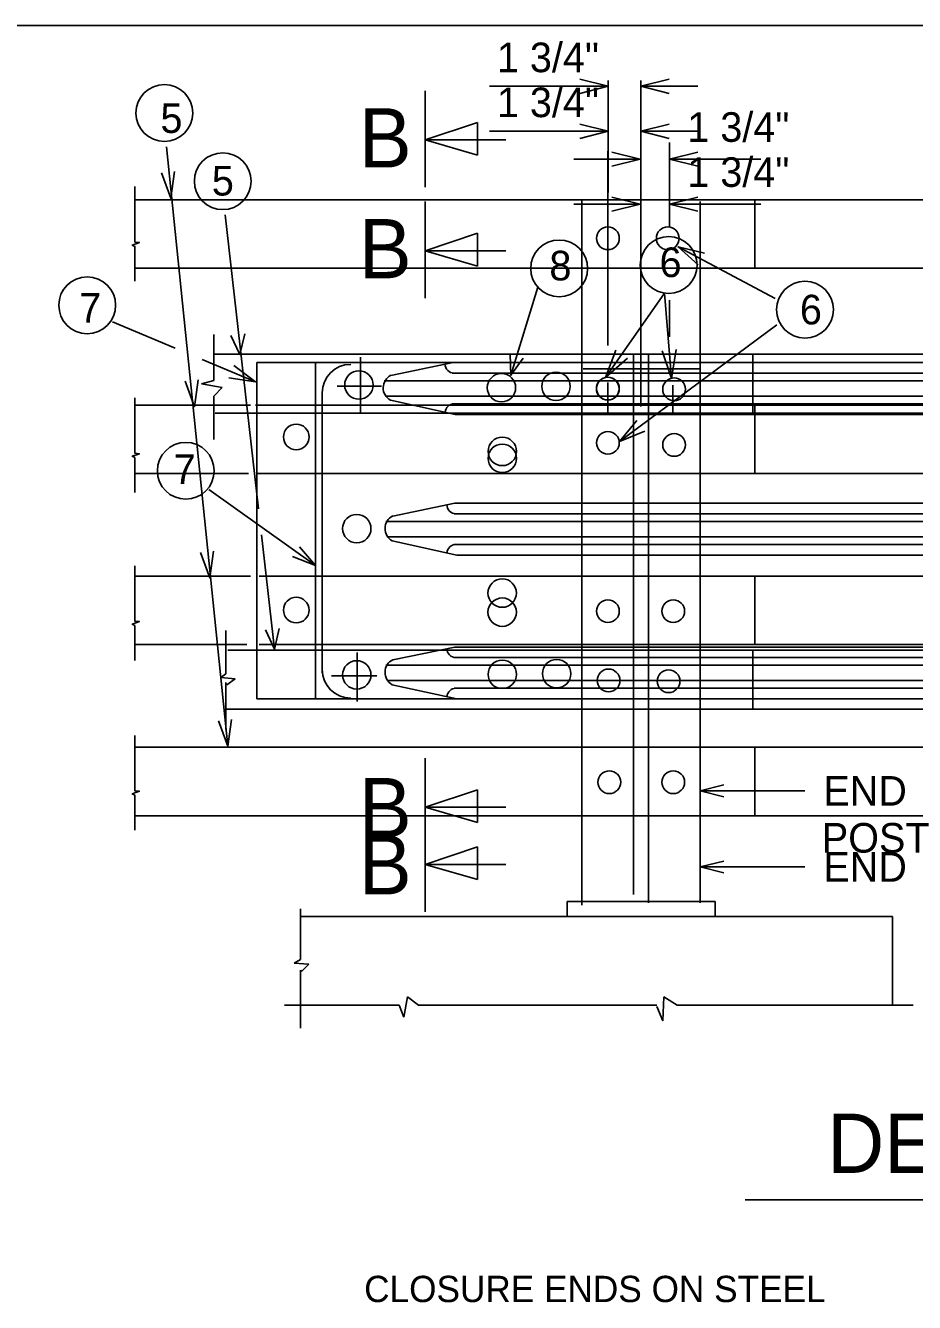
# Model space of a CAD drawing. Extents: x 1509.2 to 1521.3, y 1506 to 1514.6.
# Drawn here: x 1512.741 to 1514.148, y 1511.909 to 1513.931 of the extents above; entities that cross this region are included whole.
import ezdxf

# ---------------------------------------------------------------- set-up
doc = ezdxf.new("R2010")
doc.units = 0
for name, color, linetype in [('Level 1', 7, 'Continuous'), ('Level 2', 7, 'Continuous'), ('Level 3', 7, 'Continuous'), ('Level 4', 7, 'Continuous')]:
    doc.layers.add(name, color=color, linetype=linetype)

msp = doc.modelspace()

# ---------------------------------------------------------------- linework, layer by layer
at = {"layer": 'Level 1'}
msp.add_line((1520.7124, 1513.9308), (1510.2539, 1513.9308), dxfattribs=at)
at = {"layer": 'Level 2'}
msp.add_line((1513.8803, 1512.0718), (1515.6598, 1512.0718), dxfattribs=at)
at = {"layer": 'Level 3'}
for p, q in [((1513.6634, 1513.7634), (1513.6184, 1513.7747)), ((1513.6634, 1513.6663), (1513.6634, 1513.7725)), ((1513.7149, 1513.7634), (1513.7599, 1513.7747)), ((1513.7149, 1513.3275), (1513.7149, 1513.7725)), ((1513.4753, 1513.7634), (1513.6634, 1513.7634)), ((1513.6634, 1513.7634), (1513.6184, 1513.7522)), ((1513.7149, 1513.7634), (1513.8053, 1513.7634)), ((1513.7149, 1513.7634), (1513.7599, 1513.7522)), ((1513.7606, 1513.6128), (1513.7606, 1513.6743)), ((1513.3733, 1513.6521), (1513.3733, 1513.4993)), ((1513.6088, 1513.6481), (1513.7139, 1513.6481)), ((1513.6627, 1513.4245), (1513.6627, 1513.6608)), ((1513.7139, 1513.6481), (1513.6689, 1513.6593)), ((1513.7139, 1513.6481), (1513.6689, 1513.6368)), ((1513.7605, 1513.6481), (1513.8055, 1513.6593)), ((1513.7605, 1513.6481), (1513.9052, 1513.6481)), ((1513.7605, 1513.6481), (1513.8055, 1513.6368)), ((1513.0566, 1513.6313), (1513.1097, 1513.1658)), ((1513.3733, 1513.5743), (1513.4566, 1513.6021)), ((1513.4566, 1513.6021), (1513.4566, 1513.5501)), ((1513.4566, 1513.5501), (1513.3733, 1513.5743)), ((1513.3733, 1513.5743), (1513.5011, 1513.5743)), ((1513.5093, 1513.3773), (1513.5518, 1513.5168)), ((1513.6589, 1513.3738), (1513.7524, 1513.507)), ((1513.7524, 1513.507), (1513.7636, 1513.372)), ((1513.7606, 1513.438), (1513.7606, 1513.4958)), ((1513.0391, 1513.3691), (1513.0391, 1513.4416)), ((1513.0396, 1513.4108), (1514.3013, 1513.4108)), ((1513.2712, 1513.3186), (1513.2712, 1513.4058)), ((1513.6216, 1512.8643), (1513.6216, 1513.4107)), ((1513.6589, 1513.3738), (1513.6756, 1513.4171)), ((1513.6589, 1513.3738), (1513.6939, 1513.4042)), ((1513.7036, 1513.4107), (1513.7036, 1512.5552)), ((1513.7273, 1512.5419), (1513.7273, 1513.4107)), ((1513.7636, 1513.372), (1513.7487, 1513.4159)), ((1513.7636, 1513.372), (1513.7711, 1513.4178)), ((1513.8092, 1512.8643), (1513.8092, 1513.4107)), ((1513.8924, 1513.317), (1513.8924, 1513.4108)), ((1513.1997, 1513.3973), (1513.6219, 1513.3973)), ((1513.1997, 1512.8649), (1513.1997, 1513.3973)), ((1513.4176, 1513.3973), (1513.3193, 1513.377)), ((1513.4176, 1513.3973), (1514.3592, 1513.3973)), ((1513.6239, 1513.3873), (1513.8079, 1513.3873)), ((1513.0391, 1513.3691), (1513.0195, 1513.3634)), ((1513.0195, 1513.3634), (1513.0519, 1513.3577)), ((1513.3086, 1513.3684), (1514.3563, 1513.3684)), ((1513.4164, 1513.3807), (1514.3563, 1513.3807)), ((1513.6627, 1513.3143), (1513.6627, 1513.3658)), ((1513.0519, 1513.3577), (1513.0391, 1513.3443)), ((1513.0391, 1513.2757), (1513.0391, 1513.3443)), ((1513.2106, 1512.9063), (1513.2106, 1513.3508)), ((1513.234, 1513.3599), (1513.3042, 1513.3599)), ((1513.3108, 1513.3442), (1514.3563, 1513.3442)), ((1513.7658, 1513.3143), (1513.7658, 1513.3615)), ((1513.4208, 1513.3153), (1513.3185, 1513.3376)), ((1513.4168, 1513.332), (1514.3563, 1513.332)), ((1513.041, 1513.317), (1513.1992, 1513.317)), ((1514.3013, 1513.317), (1513.1992, 1513.317)), ((1513.4208, 1513.3153), (1514.3563, 1513.3153)), ((1513.1997, 1513.0759), (1513.0308, 1513.1961)), ((1513.4205, 1513.1746), (1513.3223, 1513.1543)), ((1513.4205, 1513.1746), (1514.3621, 1513.1746)), ((1513.3114, 1513.1457), (1514.3592, 1513.1457)), ((1513.4193, 1513.1579), (1514.3592, 1513.1579)), ((1513.1351, 1512.9437), (1513.1145, 1513.1243)), ((1513.3137, 1513.1214), (1514.3592, 1513.1214)), ((1513.1997, 1513.0759), (1513.1746, 1513.1053)), ((1513.4237, 1513.0926), (1513.3214, 1513.1148)), ((1513.4197, 1513.1093), (1514.3592, 1513.1093)), ((1513.1997, 1513.0759), (1513.1637, 1513.09)), ((1513.4237, 1513.0926), (1514.3592, 1513.0926)), ((1513.0579, 1512.9043), (1513.0579, 1512.9729)), ((1513.0613, 1512.9421), (1513.2014, 1512.9421)), ((1514.3013, 1512.9421), (1513.2014, 1512.9421)), ((1513.2656, 1512.8606), (1513.2656, 1512.9383)), ((1513.4205, 1512.9469), (1513.3223, 1512.9266)), ((1513.4205, 1512.9469), (1514.3621, 1512.9469)), ((1513.8924, 1512.8484), (1513.8924, 1512.9421)), ((1513.3114, 1512.9181), (1514.3592, 1512.9181)), ((1513.4193, 1512.9303), (1514.3592, 1512.9303)), ((1513.0579, 1512.9043), (1513.0498, 1512.8986)), ((1513.0498, 1512.8986), (1513.0728, 1512.8966)), ((1513.2251, 1512.9013), (1513.2968, 1512.9013)), ((1513.0579, 1512.8166), (1513.0579, 1512.8909)), ((1513.0728, 1512.8966), (1513.0593, 1512.8872)), ((1513.3137, 1512.8938), (1514.3592, 1512.8938)), ((1513.4237, 1512.8649), (1513.3214, 1512.8873)), ((1513.4197, 1512.8816), (1514.3592, 1512.8816)), ((1513.1997, 1512.8649), (1513.6219, 1512.8649)), ((1513.4237, 1512.8649), (1514.3592, 1512.8649)), ((1513.0583, 1512.8484), (1514.3013, 1512.8484)), ((1513.6216, 1512.5381), (1513.6216, 1512.847)), ((1513.8092, 1512.5419), (1513.8092, 1512.8508)), ((1513.3733, 1512.771), (1513.3733, 1512.6182)), ((1513.3733, 1512.6932), (1513.4566, 1512.721)), ((1513.4566, 1512.721), (1513.4566, 1512.669)), ((1513.8092, 1512.7193), (1513.8467, 1512.7286)), ((1513.8092, 1512.7193), (1513.9748, 1512.7193)), ((1513.8092, 1512.7193), (1513.8467, 1512.7098)), ((1513.4566, 1512.669), (1513.3733, 1512.6932)), ((1513.3733, 1512.6932), (1513.5011, 1512.6932)), ((1513.5983, 1512.5203), (1513.5983, 1512.5438)), ((1513.5983, 1512.5438), (1513.8326, 1512.5438)), ((1513.8326, 1512.5203), (1513.8326, 1512.5438)), ((1513.1763, 1512.4523), (1513.1763, 1512.5324)), ((1513.1763, 1512.5203), (1514.1138, 1512.5203)), ((1514.1138, 1512.3798), (1514.1138, 1512.5203)), ((1513.1763, 1512.4523), (1513.1663, 1512.4465)), ((1513.1663, 1512.4465), (1513.1891, 1512.4447)), ((1513.1763, 1512.3436), (1513.1763, 1512.4351)), ((1513.1777, 1512.4332), (1513.1763, 1512.4351)), ((1513.1891, 1512.4447), (1513.1777, 1512.4332)), ((1513.3398, 1512.3608), (1513.3455, 1512.3932)), ((1513.3455, 1512.3932), (1513.3627, 1512.3798)), ((1513.7498, 1512.355), (1513.7517, 1512.3932)), ((1513.7517, 1512.3932), (1513.7727, 1512.3798)), ((1513.1509, 1512.3798), (1513.3322, 1512.3798)), ((1513.3322, 1512.3798), (1513.3398, 1512.3608)), ((1513.3627, 1512.3798), (1513.7403, 1512.3798)), ((1513.7403, 1512.3779), (1513.7498, 1512.355)), ((1513.7727, 1512.3798), (1514.1465, 1512.3798))]:
    msp.add_line(p, q, dxfattribs=at)
for points in [[(1513.0877, 1513.4427), (1513.0803, 1513.41), (1513.0659, 1513.4403)], [(1513.5289, 1513.4043), (1513.5093, 1513.3773), (1513.5081, 1513.4108)], [(1513.1424, 1512.9764), (1513.1351, 1512.9437), (1513.1207, 1512.9739)]]:
    msp.add_lwpolyline(points, dxfattribs=at)
for centre, radius in [((1513.053, 1513.6844), 0.045), ((1513.5857, 1513.5463), 0.045), ((1513.7592, 1513.5516), 0.045), ((1513.2686, 1513.3618), 0.0225), ((1513.4943, 1513.3574), 0.0225), ((1513.5807, 1513.3596), 0.0225), ((1513.6626, 1513.3559), 0.018), ((1513.6629, 1513.3561), 0.018), ((1513.7677, 1513.355), 0.018), ((1512.9945, 1513.2259), 0.045), ((1513.4956, 1513.2566), 0.0225), ((1513.2652, 1513.1344), 0.0225), ((1513.4955, 1513.0021), 0.0225), ((1513.2652, 1512.9028), 0.0225), ((1513.4956, 1512.9036), 0.0225), ((1513.5818, 1512.9047), 0.0225), ((1513.664, 1512.894), 0.018), ((1513.759, 1512.8928), 0.018)]:
    msp.add_circle(centre, radius, dxfattribs=at)
for centre, radius, start, end in [((1513.2556, 1513.3494), 0.045, 90, 180), ((1513.4193, 1513.395), 0.0144, 181.1718, 269.587), ((1513.3296, 1513.3571), 0.0225, 117.3168, 240.3293), ((1513.4193, 1513.3179), 0.0141, 89.2579, 176.846), ((1513.4222, 1513.1723), 0.0144, 181.1718, 269.587), ((1513.3325, 1513.1344), 0.0225, 117.3168, 240.3293), ((1513.4222, 1513.0952), 0.0141, 89.2579, 176.846), ((1513.4222, 1512.9446), 0.0144, 181.1718, 269.587), ((1513.3325, 1512.9068), 0.0225, 117.3168, 240.3293), ((1513.2556, 1512.9111), 0.045, 180, 270), ((1513.4222, 1512.8675), 0.0141, 89.2579, 176.846)]:
    msp.add_arc(centre, radius, start, end, dxfattribs=at)
at = {"layer": 'Level 4'}
for p, q in [((1513.3733, 1513.8275), (1513.3733, 1513.6747)), ((1513.4753, 1513.8347), (1513.6634, 1513.8347)), ((1513.6634, 1513.8347), (1513.6184, 1513.8459)), ((1513.6634, 1513.8347), (1513.6184, 1513.8234)), ((1513.6634, 1513.7376), (1513.6634, 1513.8438)), ((1513.7149, 1513.8347), (1513.7599, 1513.8459)), ((1513.7149, 1513.3275), (1513.7149, 1513.8438)), ((1513.7149, 1513.8347), (1513.8053, 1513.8347)), ((1513.7149, 1513.8347), (1513.7599, 1513.8234)), ((1513.3733, 1513.7497), (1513.4566, 1513.7775)), ((1513.4566, 1513.7775), (1513.4566, 1513.7255)), ((1513.4566, 1513.7255), (1513.3733, 1513.7497)), ((1513.3733, 1513.7497), (1513.5011, 1513.7497)), ((1513.0609, 1512.7899), (1512.9641, 1513.7389)), ((1513.6627, 1513.4245), (1513.6627, 1513.732)), ((1513.7139, 1513.7193), (1513.6689, 1513.7306)), ((1513.7605, 1513.7193), (1513.8055, 1513.7306)), ((1513.7606, 1513.6128), (1513.7606, 1513.7455)), ((1513.6088, 1513.7193), (1513.7139, 1513.7193)), ((1513.7139, 1513.7193), (1513.6689, 1513.7081)), ((1513.7605, 1513.7193), (1513.9052, 1513.7193)), ((1513.7605, 1513.7193), (1513.8055, 1513.7081)), ((1514.3013, 1513.6548), (1512.9132, 1513.6548)), ((1513.6216, 1512.6819), (1513.6216, 1513.655)), ((1513.8092, 1512.6819), (1513.8092, 1513.6523)), ((1513.8958, 1513.5465), (1513.8958, 1513.6548)), ((1513.7739, 1513.5804), (1513.928, 1513.4989)), ((1514.3013, 1513.5465), (1512.9132, 1513.5465)), ((1513.6216, 1513.3973), (1513.6216, 1513.5481)), ((1513.8092, 1513.3973), (1513.8092, 1513.5453)), ((1513.7606, 1513.438), (1513.7606, 1513.4958)), ((1512.9774, 1513.4201), (1512.8783, 1513.4615)), ((1513.6815, 1513.2721), (1513.9302, 1513.4571)), ((1513.2712, 1513.3186), (1513.2712, 1513.4058)), ((1513.7036, 1513.4107), (1513.7036, 1512.5552)), ((1513.7273, 1512.5419), (1513.7273, 1513.4107)), ((1513.1049, 1513.3668), (1513.0203, 1513.4022)), ((1513.107, 1513.3973), (1513.6219, 1513.3973)), ((1513.107, 1512.8649), (1513.107, 1513.3973)), ((1513.4176, 1513.3973), (1513.3193, 1513.377)), ((1513.4176, 1513.3973), (1514.3592, 1513.3973)), ((1513.6239, 1513.3873), (1513.8079, 1513.3873)), ((1513.3086, 1513.3684), (1514.3563, 1513.3684)), ((1513.4164, 1513.3807), (1514.3563, 1513.3807)), ((1513.6627, 1513.3143), (1513.6627, 1513.3658)), ((1513.2106, 1512.9063), (1513.2106, 1513.3508)), ((1513.234, 1513.3599), (1513.3042, 1513.3599)), ((1513.3108, 1513.3442), (1514.3563, 1513.3442)), ((1513.7658, 1513.3143), (1513.7658, 1513.3615)), ((1513.0968, 1513.3298), (1512.9132, 1513.3298)), ((1514.3013, 1513.3298), (1513.1049, 1513.3298)), ((1513.4208, 1513.3153), (1513.3185, 1513.3376)), ((1513.4168, 1513.332), (1514.3013, 1513.332)), ((1513.8958, 1513.2215), (1513.8958, 1513.3298)), ((1513.4208, 1513.3153), (1514.3563, 1513.3153)), ((1513.094, 1513.2215), (1512.9132, 1513.2215)), ((1514.3013, 1513.2215), (1513.1077, 1513.2215)), ((1513.4205, 1513.1746), (1513.3223, 1513.1543)), ((1513.4205, 1513.1746), (1514.3621, 1513.1746)), ((1513.3114, 1513.1457), (1514.3592, 1513.1457)), ((1513.4193, 1513.1579), (1514.3592, 1513.1579)), ((1513.3137, 1513.1214), (1514.3592, 1513.1214)), ((1513.4237, 1513.0926), (1513.3214, 1513.1148)), ((1513.4197, 1513.1093), (1514.3592, 1513.1093)), ((1513.4237, 1513.0926), (1514.3592, 1513.0926)), ((1513.0968, 1513.059), (1512.9132, 1513.059)), ((1514.3013, 1513.059), (1513.1104, 1513.059)), ((1513.8958, 1512.9507), (1513.8958, 1513.059)), ((1513.0913, 1512.9507), (1512.9132, 1512.9507)), ((1514.3013, 1512.9507), (1513.1104, 1512.9507)), ((1513.2656, 1512.8606), (1513.2656, 1512.9383)), ((1513.4205, 1512.9469), (1513.3223, 1512.9266)), ((1513.4205, 1512.9469), (1514.3621, 1512.9469)), ((1513.3114, 1512.9181), (1514.3592, 1512.9181)), ((1513.4193, 1512.9303), (1514.3592, 1512.9303)), ((1513.2251, 1512.9013), (1513.2968, 1512.9013)), ((1513.3137, 1512.8938), (1514.3592, 1512.8938)), ((1513.4237, 1512.8649), (1513.3214, 1512.8873)), ((1513.4197, 1512.8816), (1514.3592, 1512.8816)), ((1513.107, 1512.8649), (1513.6219, 1512.8649)), ((1513.4237, 1512.8649), (1514.3592, 1512.8649)), ((1513.6216, 1512.7861), (1513.6216, 1512.8656)), ((1513.8092, 1512.7861), (1513.8092, 1512.8628)), ((1514.3013, 1512.7882), (1512.9132, 1512.7882)), ((1513.8958, 1512.6798), (1513.8958, 1512.7882)), ((1514.3013, 1512.6798), (1512.9132, 1512.6798)), ((1513.3733, 1512.6806), (1513.3733, 1512.5278)), ((1513.8092, 1512.5419), (1513.8092, 1512.6792)), ((1513.6216, 1512.5381), (1513.6216, 1512.671)), ((1513.3733, 1512.6028), (1513.4566, 1512.6306)), ((1513.4566, 1512.6306), (1513.4566, 1512.5786)), ((1513.4566, 1512.5786), (1513.3733, 1512.6028)), ((1513.3733, 1512.6028), (1513.5011, 1512.6028)), ((1513.8092, 1512.5987), (1513.8467, 1512.608)), ((1513.8092, 1512.5987), (1513.9748, 1512.5987)), ((1513.8092, 1512.5987), (1513.8467, 1512.5893)), ((1513.5983, 1512.5203), (1513.5983, 1512.5438)), ((1513.5983, 1512.5438), (1513.8326, 1512.5438)), ((1513.8326, 1512.5203), (1513.8326, 1512.5438)), ((1513.1763, 1512.4523), (1513.1763, 1512.5324)), ((1513.1763, 1512.5203), (1514.1138, 1512.5203)), ((1514.1138, 1512.3798), (1514.1138, 1512.5203)), ((1513.1763, 1512.4523), (1513.1663, 1512.4465)), ((1513.1663, 1512.4465), (1513.1891, 1512.4447)), ((1513.1763, 1512.3436), (1513.1763, 1512.4351)), ((1513.1777, 1512.4332), (1513.1763, 1512.4351)), ((1513.1891, 1512.4447), (1513.1777, 1512.4332)), ((1513.3398, 1512.3608), (1513.3455, 1512.3932)), ((1513.3455, 1512.3932), (1513.3627, 1512.3798)), ((1513.7498, 1512.355), (1513.7517, 1512.3932)), ((1513.7517, 1512.3932), (1513.7727, 1512.3798)), ((1513.1509, 1512.3798), (1513.3322, 1512.3798)), ((1513.3322, 1512.3798), (1513.3398, 1512.3608)), ((1513.3627, 1512.3798), (1513.7403, 1512.3798)), ((1513.7403, 1512.3779), (1513.7498, 1512.355)), ((1513.7727, 1512.3798), (1514.1465, 1512.3798))]:
    msp.add_line(p, q, dxfattribs=at)
for points in [[(1512.9768, 1513.7), (1512.9707, 1513.6575), (1512.9561, 1513.6979)], [(1512.914, 1513.5261), (1512.914, 1513.5812), (1512.9098, 1513.5833), (1512.9211, 1513.5874), (1512.914, 1513.5881), (1512.914, 1513.676)], [(1513.8059, 1513.5518), (1513.7739, 1513.5804), (1513.8156, 1513.5702)], [(1513.0705, 1513.3925), (1513.1049, 1513.3668), (1513.0624, 1513.3733)], [(1513.0143, 1513.3697), (1513.0081, 1513.3272), (1512.9935, 1513.3676)], [(1512.914, 1513.1917), (1512.914, 1513.2468), (1512.9098, 1513.2489), (1512.9211, 1513.253), (1512.914, 1513.2537), (1512.914, 1513.3416)], [(1513.7212, 1513.2886), (1513.6815, 1513.2721), (1513.7088, 1513.3053)], [(1513.0384, 1513.0988), (1513.0323, 1513.0563), (1513.0177, 1513.0968)], [(1512.914, 1512.9258), (1512.914, 1512.9808), (1512.9098, 1512.983), (1512.9211, 1512.9871), (1512.914, 1512.9878), (1512.914, 1513.0757)], [(1513.0671, 1512.8324), (1513.0609, 1512.7899), (1513.0463, 1512.8303)], [(1512.914, 1512.6572), (1512.914, 1512.7123), (1512.9098, 1512.7144), (1512.9211, 1512.7185), (1512.914, 1512.7192), (1512.914, 1512.8071)]]:
    msp.add_lwpolyline(points, dxfattribs=at)
for centre, radius in [((1512.9606, 1513.7923), 0.045), ((1513.6629, 1513.594), 0.018), ((1513.7576, 1513.594), 0.018), ((1512.8383, 1513.488), 0.045), ((1513.9749, 1513.4811), 0.045), ((1513.2686, 1513.3618), 0.0225), ((1513.1694, 1513.2795), 0.0203), ((1513.6629, 1513.2702), 0.018), ((1513.7677, 1513.2669), 0.018), ((1513.4956, 1513.2457), 0.0225), ((1513.2652, 1513.1344), 0.0225), ((1513.4955, 1513.0323), 0.0225), ((1513.1694, 1513.0054), 0.0203), ((1513.6629, 1513.0037), 0.018), ((1513.7664, 1513.0037), 0.018), ((1513.2652, 1512.9028), 0.0225), ((1513.6651, 1512.7329), 0.018), ((1513.7664, 1512.7329), 0.018)]:
    msp.add_circle(centre, radius, dxfattribs=at)
for centre, radius, start, end in [((1513.2556, 1513.3494), 0.045, 90, 180), ((1513.4193, 1513.395), 0.0144, 181.1718, 269.587), ((1513.3296, 1513.3571), 0.0225, 117.3168, 240.3293), ((1513.4193, 1513.3179), 0.0141, 89.2579, 176.846), ((1513.4222, 1513.1723), 0.0144, 181.1718, 269.587), ((1513.3325, 1513.1344), 0.0225, 117.3168, 240.3293), ((1513.4222, 1513.0952), 0.0141, 89.2579, 176.846), ((1513.4222, 1512.9446), 0.0144, 181.1718, 269.587), ((1513.3325, 1512.9068), 0.0225, 117.3168, 240.3293), ((1513.2556, 1512.9111), 0.045, 180, 270), ((1513.4222, 1512.8675), 0.0141, 89.2579, 176.846)]:
    msp.add_arc(centre, radius, start, end, dxfattribs=at)

# ---------------------------------------------------------------- texts
at = {"layer": 'Level 2'}
for s, height, p in [('DETAIL AT END POST', 0.09375, (1514.01, 1512.1144)), ('CLOSURE ENDS ON STEEL ', 0.041667, (1513.2769, 1511.9098))]:
    msp.add_text(s, height=height, rotation=360, dxfattribs=at).set_placement(p)
at = {"layer": 'Level 3'}
for p in [(1513.4871, 1513.7858), (1513.7886, 1513.6754)]:
    msp.add_text('1 3/4"', height=0.04687, dxfattribs=at).set_placement(p)
for s, height, p in [('5', 0.0469, (1513.0357, 1513.6617)), ('B', 0.0938, (1513.2685, 1513.5307)), ('8', 0.0469, (1513.5702, 1513.5273)), ('6', 0.0469, (1513.7447, 1513.5326)), ('7', 0.0469, (1512.9753, 1513.2051)), ('B', 0.0938, (1513.2685, 1512.6458)), ('END', 0.04687, (1514.004, 1512.6958)), ('POST', 0.04687, (1514.0016, 1512.6214))]:
    msp.add_text(s, height=height, rotation=0, dxfattribs=at).set_placement(p)
at = {"layer": 'Level 4'}
for p in [(1513.4871, 1513.857), (1513.7886, 1513.7467)]:
    msp.add_text('1 3/4"', height=0.04687, dxfattribs=at).set_placement(p)
for s, height, p in [('5', 0.0469, (1512.9543, 1513.7608)), ('B', 0.0938, (1513.2685, 1513.7061)), ('7', 0.0469, (1512.8256, 1513.4605)), ('6', 0.0469, (1513.9669, 1513.4577)), ('B', 0.0938, (1513.2685, 1512.5553)), ('END', 0.04687, (1514.004, 1512.5753))]:
    msp.add_text(s, height=height, rotation=0, dxfattribs=at).set_placement(p)

doc.saveas('drawing.dxf')
